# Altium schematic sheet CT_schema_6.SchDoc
size 278 x 161 mm
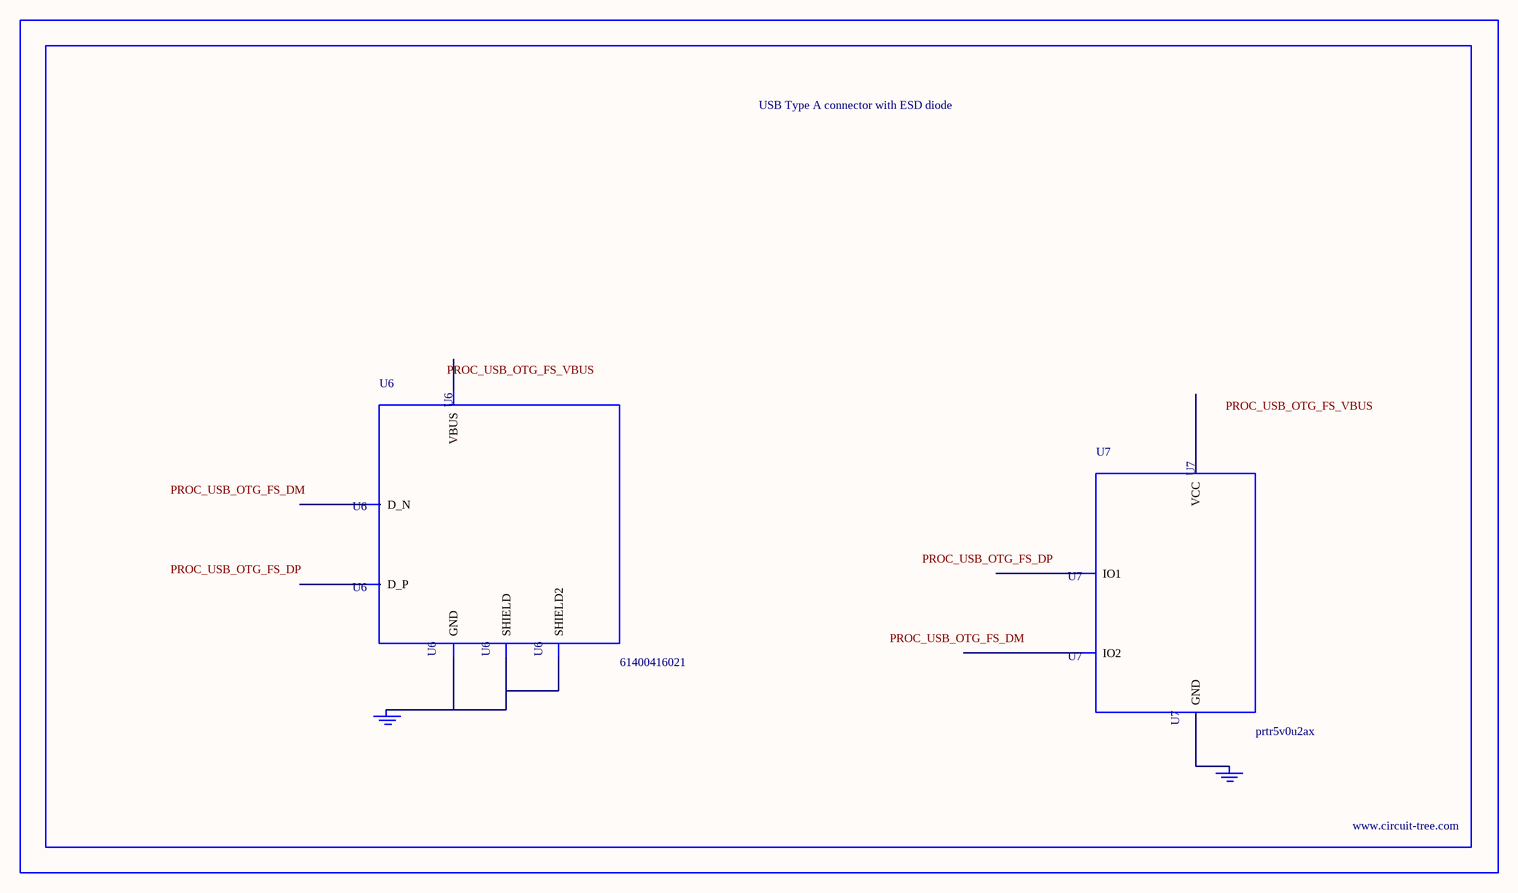
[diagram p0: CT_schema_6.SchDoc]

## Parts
BORDER5  (no value)
GND_INSTANCE_5_0  (no value)
GND_INSTANCE_5_1  (no value)
U6  61400416021  [USB-A-H]
U7  prtr5v0u2ax  [SOT143B]

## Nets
NetGND_INSTANCE_5_0_0: GND_INSTANCE_5_0.0(GND) U6.4(GND) U6.5(SHIELD) U6.6(SHIELD2)
NetGND_INSTANCE_5_1_0: GND_INSTANCE_5_1.0(GND) U7.1(GND)

Not connected (* = marked no-connect by the designer): U6 1(VBUS) 2(D_N) 3(D_P); U7 2(IO1) 3(IO2) 4(VCC)

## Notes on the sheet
- Labels drawn without touching a wire or pin: PROC_USB_OTG_FS_DM, PROC_USB_OTG_FS_DP, PROC_USB_OTG_FS_VBUS

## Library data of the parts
BORDER5 = BORDER_PAGE5
GND_INSTANCE_5_0 GND_INSTANCE_5_1 = GND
